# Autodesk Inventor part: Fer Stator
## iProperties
Shininess: 64.0
Length Units: 11269
Angle Units: 11279
Time Units: 11290
Mass Units: 11283
Length Display Precision: 3
Angle Display Precision: 2
Compacted: True
Part Number: Fer Stator
Document SubType Name: Modeling
Created: 2005-01
Material: Par défaut
Designer: lolo (Laurent Moretti)
Density: 0.0
Volumn: 0.0
Area: 0.0
PropertySet Name: Model Information
Control State: 0
Master: False
Checked Out: False
Author: lolo (Laurent Moretti)
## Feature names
1. Extrusion1
2. Extrusion2
3. Réseau circulaire1 [Circular Pattern]
4. Révolution1 [Revolution]
5. Symétrie1 [Mirror]
